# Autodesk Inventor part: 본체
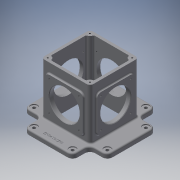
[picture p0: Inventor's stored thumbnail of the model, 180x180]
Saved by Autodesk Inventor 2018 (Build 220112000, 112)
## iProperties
Created: 2018-09
Part Number: 본체
Material: 알루미늄 6061
Document SubType Name: Modeling
Designer: mduedu
Density: 2.71 g/cm^3
Mass: 1126.64 g
Surface Area: 1144.86 cm^2
Volume: 415.735 cm^3
Appearance: 기본값
Author: mduedu
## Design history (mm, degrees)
sketch "스케치1"
  geometry: L1 (90, 52.5)-(-90, 52.5); L2 (-90, 52.5)-(-90, -52.5); L3 (-90, -52.5)-(90, -52.5); L4 (90, -52.5)-(90, 52.5); L5 (90, 52.5)-(-90, -52.5); L6 (-90, 52.5)-(90, -52.5); L7 (-52.5, -90)-(52.5, -90); L8 (52.5, -90)-(52.5, 90); L9 (52.5, 90)-(-52.5, 90); L10 (-52.5, 90)-(-52.5, -90); L11 (-52.5, -90)-(52.5, 90); L12 (52.5, -90)-(-52.5, 90); 1 further point
  constraints: 24 end point, 4 midpoint, 4 parallel, 2 horizontal, 2 perpendicular
  dimensions: "d0" = 180 distance of L3.end L2.end; "d1" = 105 distance of L2.end L1.end; "d105" = 105 distance of L9.end L8.end; "d106" = 180 distance of L8.end L7.end
extrude "돌출1" new body sketch "스케치1" distance "d2" = 10; taper "d3" = 0 deg
fillet "모깎기16" dims "d107" = 11
sketch "스케치2"
  geometry: L1 (-52.5, -52.5)-(52.5, -52.5); L2 (52.5, -52.5)-(52.5, 52.5); L3 (52.5, 52.5)-(-52.5, 52.5); L4 (-52.5, 52.5)-(-52.5, -52.5); L5 (-52.5, -52.5)-(52.5, 52.5); L6 (52.5, -52.5)-(-52.5, 52.5); 1 further point
  constraints: 12 end point, 2 midpoint, 2 parallel, 1 horizontal, 1 perpendicular
  dimensions: "d4" = 105 distance of L3.end L2.end; "d5" = 105 distance of L2.end L1.end
extrude "돌출2" join sketch "스케치2" distance "d6" = 110; taper "d7" = 0 deg
sketch "스케치14"
  geometry: L1 (-52.5, 52.5)-(52.5, 52.5) reference; L2 (52.5, 52.5)-(52.5, -52.5) reference; L3 (52.5, -52.5)-(-52.5, -52.5) reference; L4 (-52.5, -52.5)-(-52.5, 52.5) reference; L5 (46.5, 46.5)-(-46.5, 46.5); L6 (-46.5, 46.5)-(-46.5, -46.5); L7 (-46.5, -46.5)-(46.5, -46.5); L8 (46.5, -46.5)-(46.5, 46.5); 1 further point
  constraints: 8 end point, 3 other
  dimensions: "d85" = 6 distance between parallel lines of L5 L1
extrude "돌출10" cut sketch "스케치14" extent not by distance; stored distance "d86" = 10; taper "d87" = 0 deg
fillet "모깎기1" dims "d12" = 7
sketch "스케치15"
  geometry: A1 r 7 centre (-45.5, 45.5) between (-45.5, 52.5) and (-52.5, 45.5) reference; A2 r 7 centre (45.5, 45.5) between (52.5, 45.5) and (45.5, 52.5) reference; A3 r 7 centre (45.5, -45.5) between (45.5, -52.5) and (52.5, -45.5) reference; A4 r 7 centre (-45.5, -45.5) between (-52.5, -45.5) and (-45.5, -52.5) reference; 5 further points
  constraints: 4 coincident, 4 vertical alignment, 8 other
extrude "돌출11" join sketch "스케치15" stored distance "d88" = 10; taper "d89" = 0 deg
fillet "모깎기15" dims "d90" = 3
sketch "스케치6"
  geometry: L1 (50, 20)-(130, 20); L2 (130, 20)-(130, 100); L3 (130, 100)-(50, 100); L4 (50, 100)-(50, 20); L5 (50, 20)-(130, 100); L6 (130, 20)-(50, 100); L7 (0, 0)-(180, 0) reference; 4 further points
  constraints: 12 end point, 4 midpoint, 2 parallel, 1 horizontal, 1 perpendicular, 1 vertical alignment
  dimensions: "d25" = 80 distance of L3.end L2.end; "d26" = 80 distance of L2.end L1.end; "d27" = 60 distance of point (90, 0) point (90, 60)
extrude "돌출6" join sketch "스케치6" distance "d28" = 3; taper "d29" = 0 deg
fillet "모깎기7" dims "d30" = 8
sketch "스케치7"
  geometry: C1 r 32.5 at (90, 60); 1 further point
  constraints: 1 centre point, 1 vertical alignment
  dimensions: "d32" = 65 diameter of C1; "d33" = 60 distance of C1.centre point (90, 0)
extrude "돌출7" cut sketch "스케치7" stored distance "d34" = 3; taper "d35" = 0 deg
fillet "모깎기9" dims "d36" = 3
sketch "스케치8"
  geometry: L1 (5.5, 10)-(85.5, 10); L2 (85.5, 10)-(85.5, 90); L3 (85.5, 90)-(5.5, 90); L4 (5.5, 90)-(5.5, 10); L5 (5.5, 10)-(85.5, 90); L6 (85.5, 10)-(5.5, 90); L7 (-7, -10)-(98, -10) reference; C1 r 32.5 at (45.5, 50); 4 further points
  constraints: 12 end point, 4 midpoint, 2 parallel, 1 centre point, 1 coincident, 1 horizontal, 1 perpendicular, 1 vertical alignment
  dimensions: "d37" = 80 distance of L3.end L2.end; "d38" = 80 distance of L2.end L1.end; "d39" = 60 distance from line of point (45.5, 50) L7; "d40" = 65 diameter of C1
extrude "돌출8" join sketch "스케치8" distance "d41" = 3; taper "d42" = 0 deg
fillet "모깎기10" dims "d43" = 8
extrude "돌출9" cut sketch "스케치8" stored distance "d44" = 3; taper "d45" = 0 deg
fillet "모깎기11" dims "d46" = 3
sketch "스케치9"
  geometry: L1 (50, 92)-(50, 28) reference; L2 (58, 20)-(122, 20) reference; L3 (130, 28)-(130, 92) reference; L4 (122, 100)-(58, 100) reference; C1 r 32.5 at (90, 60) reference; A1 r 8 centre (58, 92) between (58, 100) and (50, 92) reference; A2 r 8 centre (58, 28) between (50, 28) and (58, 20) reference; A3 r 8 centre (122, 28) between (122, 20) and (130, 28) reference; A4 r 8 centre (122, 92) between (130, 92) and (122, 100) reference; 5 further points
  constraints: 4 coincident
hole "구멍1" sketch "스케치9" at (58, 92), (122, 92), (122, 28), (58, 28) diameter "d47" = 3.242; stored, may be unused: countersink angle "d51" = 90 deg, drill point angle "d53" = 118 deg; dims "d48" = 6, "d49" = 4, "d50" = 2, "d52" = 9
sketch "스케치10"
  geometry: L1 (13.5, 10)-(77.5, 10) reference; L2 (85.5, 18)-(85.5, 82) reference; L3 (77.5, 90)-(13.5, 90) reference; L4 (5.5, 82)-(5.5, 18) reference; C1 r 32.5 at (45.5, 50) reference; A1 r 8 centre (13.5, 18) between (5.5, 18) and (13.5, 10) reference; A2 r 8 centre (77.5, 18) between (77.5, 10) and (85.5, 18) reference; A3 r 8 centre (77.5, 82) between (85.5, 82) and (77.5, 90) reference; A4 r 8 centre (13.5, 82) between (13.5, 90) and (5.5, 82) reference; 5 further points
  constraints: 4 coincident
hole "구멍2" sketch "스케치10" at (13.5, 82), (77.5, 82), (77.5, 18), (13.5, 18) diameter "d54" = 3.242; stored, may be unused: countersink angle "d58" = 90 deg, drill point angle "d60" = 118 deg; dims "d55" = 6, "d56" = 4, "d57" = 2, "d59" = 9
fillet "모깎기12" dims "d68" = 11
sketch "스케치16"
  geometry: A1 r 11 centre (-79, 41.5) between (-79, 52.5) and (-90, 41.5) reference; A2 r 11 centre (-79, -41.5) between (-90, -41.5) and (-79, -52.5) reference; A3 r 11 centre (79, 41.5) between (90, 41.5) and (79, 52.5) reference; A4 r 11 centre (79, -41.5) between (79, -52.5) and (90, -41.5) reference; A5 r 11 centre (-41.5, 79) between (-41.5, 90) and (-52.5, 79) reference; A6 r 11 centre (41.5, 79) between (52.5, 79) and (41.5, 90) reference; A7 r 11 centre (41.5, -79) between (41.5, -90) and (52.5, -79) reference; A8 r 11 centre (-41.5, -79) between (-52.5, -79) and (-41.5, -90) reference; 9 further points
  constraints: 8 coincident
hole "구멍5" sketch "스케치16" at (-79, 41.5), (79, 41.5), (79, -41.5), (-79, -41.5), (41.5, 79), (-41.5, 79), (-41.5, -79), (41.5, -79) diameter "d91" = 6.6; stored, may be unused: countersink angle "d95" = 90 deg, drill point angle "d97" = 118 deg; dims "d92" = 6, "d93" = 15, "d94" = 2, "d96" = 8
fillet "모깎기13" dims "d77" = 3
chamfer "모따기1" distance "d79" = 1; stored, may be unused: second distance "d80" = 2, angle "d81" = 45 deg
sketch "스케치17"
  geometry: A1 r 7 centre (-45.5, 45.5) between (-45.5, 52.5) and (-52.5, 45.5) reference; A2 r 7 centre (-45.5, -45.5) between (-52.5, -45.5) and (-45.5, -52.5) reference; A3 r 7 centre (45.5, -45.5) between (45.5, -52.5) and (52.5, -45.5) reference; A4 r 7 centre (45.5, 45.5) between (52.5, 45.5) and (45.5, 52.5) reference; 5 further points
  constraints: 4 coincident
hole "구멍6" sketch "스케치17" at (-45.5, 45.5), (45.5, 45.5), (45.5, -45.5), (-45.5, -45.5) diameter "d98" = 3.242; stored, may be unused: countersink angle "d102" = 90 deg, drill point angle "d104" = 118 deg; dims "d99" = 8, "d100" = 15, "d101" = 2, "d103" = 10
sketch "스케치13"
  geometry: L1 (90, -41.5)-(90, 41.5) reference; 2 further points
  constraints: 1 horizontal alignment, 1 other
  dimensions: "d82" = 11 distance from line of point (79, 0) L1
feature "엠보싱1" sketch "스케치13" dims "d0" = 180, "d1" = 105, "d83" = 0.5, "d84" = 0
node "솔리드1"
mirror "대칭1"
mirror "대칭4"
mirror "대칭2"
mirror "대칭5"
node "투영된 루프2"
node "투영된 루프3"
node "투영된 루프6"
